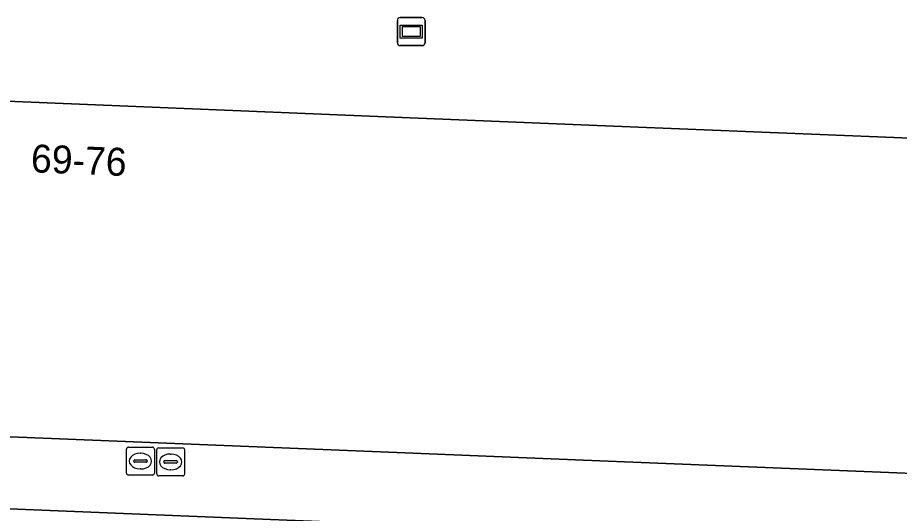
# Model space of a CAD drawing. Extents: x 160888 to 161385, y 386490 to 386908.
# Drawn here: x 161238.42 to 161269.97, y 386816.14 to 386833.87 of the extents above; entities that cross this region are included whole.
import ezdxf

# ---------------------------------------------------------------- set-up
doc = ezdxf.new("R2010")
doc.units = 0
for name, color, linetype in [('IMGEO_Pand', 7, 'Continuous'), ('IMGEO_Pand_nummerreeks', 7, 'Continuous'), ('IMGEO_Reclamebord', 7, 'Continuous'), ('IMGEO_Rijbaan_lokaal_open', 7, 'Continuous'), ('IMGEO_Rioolput', 7, 'Continuous'), ('IMGEO_Voetgangersgebied_open', 7, 'Continuous')]:
    doc.layers.add(name, color=color, linetype=linetype)

msp = doc.modelspace()

# ---------------------------------------------------------------- linework, layer by layer
at = {"layer": 'IMGEO_Pand'}
msp.add_lwpolyline([(161281.723, 386829.096), (161269.188, 386829.608), (161259.736, 386829.994), (161252.467, 386830.291), (161238.036, 386830.88), (161223.504, 386831.473), (161216.339, 386831.766), (161201.804, 386832.359), (161201.32, 386820.359), (161215.857, 386819.772), (161223.022, 386819.483), (161237.554, 386818.897), (161251.986, 386818.314), (161259.254, 386818.021), (161268.706, 386817.64), (161273.381, 386817.451), (161278.601, 386817.252), (161278.605, 386817.352), (161281.256, 386817.22)], close=True, dxfattribs=at)
at = {"layer": 'IMGEO_Reclamebord'}
for p, q in [((161252.008, 386832.973), (161252.008, 386833.773)), ((161252.008, 386833.773), (161252.008, 386832.973)), ((161252.108, 386833.873), (161252.898, 386833.873)), ((161252.898, 386833.873), (161252.108, 386833.873)), ((161252.998, 386833.773), (161252.998, 386832.973)), ((161252.998, 386832.973), (161252.998, 386833.773)), ((161252.898, 386832.873), (161252.108, 386832.873)), ((161252.108, 386832.873), (161252.898, 386832.873))]:
    msp.add_line(p, q, dxfattribs=at)
for points in [[(161252.109, 386833.605), (161252.897, 386833.605), (161252.897, 386833.141), (161252.109, 386833.141), (161252.109, 386833.605)], [(161252.174, 386833.54), (161252.174, 386833.206), (161252.832, 386833.206), (161252.832, 386833.54), (161252.174, 386833.54)]]:
    msp.add_lwpolyline(points, dxfattribs=at)
for centre, start, end in [((161252.108, 386833.773), 90, 180), ((161252.108, 386833.773), 90, 180), ((161252.898, 386833.773), 0, 90), ((161252.898, 386833.773), 360, 90), ((161252.108, 386832.973), 180, 270), ((161252.108, 386832.973), 180, 270), ((161252.898, 386832.973), 270, 0), ((161252.898, 386832.973), 270, 0)]:
    msp.add_arc(centre, 0.1, start, end, dxfattribs=at)
at = {"layer": 'IMGEO_Rijbaan_lokaal_open'}
msp.add_lwpolyline([(161203.836, 386811.625), (161237.38, 386810.438), (161267.443, 386809.136), (161267.641, 386815.102), (161201.283, 386817.8), (161192.377, 386818.162), (161191.164, 386788.243), (161189.757, 386753.134), (161218.231, 386752.088), (161265.005, 386750.043), (161265.23, 386755.803), (161265.263, 386756.048), (161236.981, 386757.263), (161201.197, 386758.615)], dxfattribs=at)
at = {"layer": 'IMGEO_Rioolput'}
for p, q in [((161242.313, 386817.582), (161242.313, 386818.434)), ((161242.388, 386818.508), (161243.24, 386818.508)), ((161242.801, 386818.288), (161242.826, 386818.288)), ((161243.314, 386818.434), (161243.314, 386817.582)), ((161243.395, 386817.555), (161243.395, 386818.407)), ((161243.47, 386818.481), (161244.322, 386818.481)), ((161243.883, 386818.261), (161243.908, 386818.261)), ((161244.396, 386818.407), (161244.396, 386817.555)), ((161242.572, 386818.002), (161242.572, 386818.014)), ((161243.01, 386817.965), (161242.612, 386817.965)), ((161242.615, 386818.051), (161243.013, 386818.051)), ((161243.056, 386818.014), (161243.056, 386818.002)), ((161243.654, 386817.975), (161243.654, 386817.987)), ((161244.092, 386817.938), (161243.694, 386817.938)), ((161243.697, 386818.024), (161244.095, 386818.024)), ((161244.138, 386817.987), (161244.138, 386817.975)), ((161242.824, 386817.728), (161242.799, 386817.728)), ((161243.906, 386817.701), (161243.881, 386817.701)), ((161243.24, 386817.508), (161242.388, 386817.508)), ((161244.322, 386817.481), (161243.47, 386817.481))]:
    msp.add_line(p, q, dxfattribs=at)
for points in [[(161242.313, 386817.582), (161242.313, 386818.434)], [(161242.388, 386818.508), (161243.24, 386818.508)], [(161243.314, 386818.434), (161243.314, 386817.582)], [(161243.395, 386817.555), (161243.395, 386818.407)], [(161243.47, 386818.481), (161244.322, 386818.481)], [(161244.396, 386818.407), (161244.396, 386817.555)], [(161243.24, 386817.508), (161242.388, 386817.508)], [(161244.322, 386817.481), (161243.47, 386817.481)]]:
    msp.add_lwpolyline(points, dxfattribs=at)
for centre, radius, start, end in [((161242.39, 386818.432), 0.0765, 91.552, 178.448), ((161242.39, 386818.432), 0.0765, 91.552, 178.448), ((161243.238, 386818.432), 0.0765, 1.552, 88.448), ((161243.238, 386818.432), 0.0765, 1.552, 88.448), ((161243.472, 386818.405), 0.0765, 91.552, 178.448), ((161243.472, 386818.405), 0.0765, 91.552, 178.448), ((161244.32, 386818.405), 0.0765, 1.552, 88.448), ((161244.32, 386818.405), 0.0765, 1.552, 88.448), ((161242.612, 386818.011), 0.0403, 85.8775, 175.7526), ((161242.609, 386818.001), 0.0366, 178.938, 274.7102), ((161243.013, 386818.008), 0.043, 264.8664, 352.4533), ((161243.017, 386818.013), 0.0386, 1.7309, 96.639), ((161243.694, 386817.984), 0.0403, 85.8775, 175.7526), ((161243.691, 386817.974), 0.0366, 178.938, 274.7102), ((161244.095, 386817.981), 0.043, 264.8664, 352.4533), ((161244.099, 386817.986), 0.0386, 1.7309, 96.639), ((161242.39, 386817.584), 0.0765, 181.552, 268.448), ((161242.39, 386817.584), 0.0765, 181.552, 268.448), ((161243.238, 386817.584), 0.0765, 271.552, 358.448), ((161243.238, 386817.584), 0.0765, 271.552, 358.448), ((161243.472, 386817.557), 0.0765, 181.552, 268.448), ((161243.472, 386817.557), 0.0765, 181.552, 268.448), ((161244.32, 386817.557), 0.0765, 271.552, 358.448), ((161244.32, 386817.557), 0.0765, 271.552, 358.448)]:
    msp.add_arc(centre, radius, start, end, dxfattribs=at)
for centre, major_axis, ratio, start_param, end_param in [((161242.8, 386818.008), (-0.387, 0.002), 0.722429, 4.712389, 7.853982), ((161242.825, 386818.008), (-0.39, 0.002), 0.717154, 1.570796, 4.712389), ((161243.882, 386817.981), (-0.387, 0.002), 0.722429, 4.712389, 7.853982), ((161243.907, 386817.981), (-0.39, 0.002), 0.717154, 1.570796, 4.712389)]:
    msp.add_ellipse(centre, major_axis=major_axis, ratio=ratio, start_param=start_param, end_param=end_param, dxfattribs=at)
at = {"layer": 'IMGEO_Voetgangersgebied_open'}
for points in [[(161128.442, 386835.301), (161139.684, 386834.849), (161143.958, 386834.674), (161161.282, 386833.963), (161170.867, 386833.628), (161190.117, 386832.93), (161199.627, 386832.585), (161199.621, 386832.448), (161201.804, 386832.359), (161216.339, 386831.766), (161223.504, 386831.473), (161238.036, 386830.88), (161252.467, 386830.291), (161259.736, 386829.994), (161269.188, 386829.608), (161281.723, 386829.096), (161281.825, 386831.496), (161282.087, 386837.641), (161282.13, 386838.652), (161282.19, 386840.045), (161203.707, 386843.159), (161196.993, 386842.62), (161194.586, 386842.427), (161120.067, 386845.369)], [(161273.381, 386817.451), (161268.706, 386817.64), (161259.254, 386818.021), (161251.986, 386818.314), (161237.554, 386818.897), (161223.022, 386819.483), (161215.857, 386819.772), (161201.32, 386820.359), (161201.283, 386817.8), (161267.641, 386815.102), (161268.448, 386815.144), (161268.216, 386809.147), (161267.443, 386809.136), (161267.342, 386808.187), (161267.161, 386803.187), (161267.905, 386803.135), (161267.691, 386797.336), (161266.946, 386797.398), (161266.523, 386787.517), (161267.255, 386787.478), (161286.841, 386786.774)]]:
    msp.add_lwpolyline(points, dxfattribs=at)

# ---------------------------------------------------------------- texts
at = {"layer": 'IMGEO_Pand_nummerreeks'}
msp.add_text('69-76', height=1, rotation=357.6628, dxfattribs=at).set_placement((161238.881, 386828.343))

doc.saveas('drawing.dxf')
